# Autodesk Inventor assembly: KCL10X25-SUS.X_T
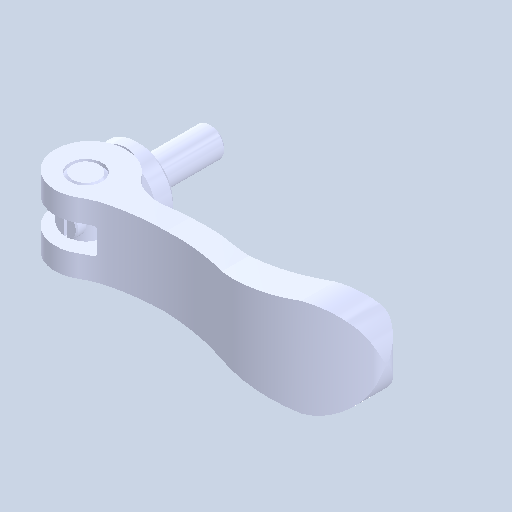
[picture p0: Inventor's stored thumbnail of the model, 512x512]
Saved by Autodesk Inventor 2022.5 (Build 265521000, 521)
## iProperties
Created: 2024-08
Part Number: KCL10X25-SUS.X_T
Document SubType Name: Assembly
Designer: ImaoCorp
Author: ImaoCorp
Sending System: SOLIDWORKS 2022-2022290
MC: AMD64
MC_MODEL: Intel64 Family 6 Model 60 Stepping 3, GenuineIntel
OS: Windows_NT
FRU: Parasolid Version 33.1, build 260,  4-25-2022
FORMAT: text
GUISE: transmit
KEY: FILEKCL10X25-SUS.x_t
DATE: Thu Aug 29 10:50:54 2024
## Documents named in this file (5)
- Y:\5.更新分\2024年対応\1001_KCL\データ\kcl10x25-sus\KCL10X25-SUS.X_T.iam
- Y:\5.更新分\2024年対応\1001_KCL\データ\kcl10x25-sus\KCL10X25-SUS_01.ipt
- Y:\5.更新分\2024年対応\1001_KCL\データ\kcl10x25-sus\KCL10X25-SUS_02.ipt
- Y:\5.更新分\2024年対応\1001_KCL\データ\kcl10x25-sus\KCL10X25-SUS_03.ipt
- Y:\5.更新分\2024年対応\1001_KCL\データ\kcl10x25-sus\KCL10X25-SUS_04.ipt
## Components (4 placed, 4 different names)
1. KCL10X25-SUS_01
2. KCL10X25-SUS_02
3. KCL10X25-SUS_03
4. KCL10X25-SUS_04
